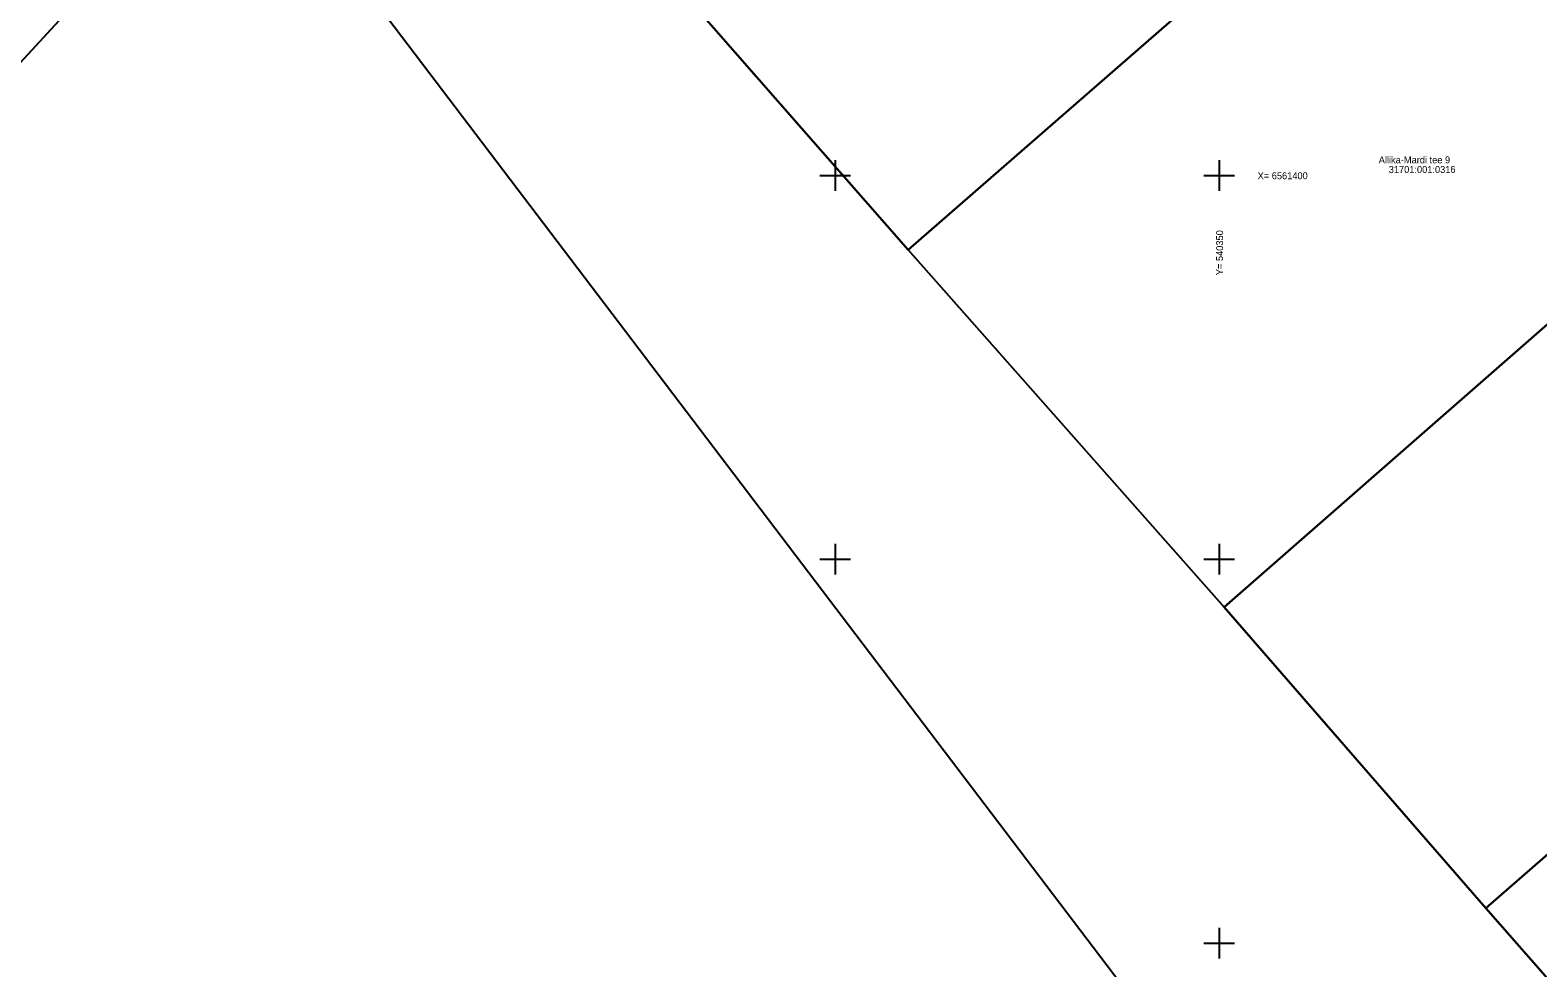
# Model space of a CAD drawing. Extents: x 538599 to 541973, y 6559689 to 6564516.
# Drawn here: x 540195.2 to 540391.5, y 6561296.8 to 6561418.9 of the extents above; entities that cross this region are included whole.
import ezdxf

# ---------------------------------------------------------------- set-up
doc = ezdxf.new("R2010")
doc.units = 0
for name, color, linetype in [('PIIR', 7, 'Continuous'), ('VORK', 7, 'Continuous'), ('VORMISTUS', 7, 'Continuous')]:
    doc.layers.add(name, color=color, linetype=linetype)

msp = doc.modelspace()

# ---------------------------------------------------------------- linework, layer by layer
at = {"layer": 'PIIR'}
msp.add_lwpolyline([(540274.62, 6561658.98), (540308.95, 6561626.96), (540342.1, 6561660.8), (540380.29, 6561616.49), (540315.96, 6561547.42), (540242.15, 6561467.11), (540086.59, 6561298.21), (539860.44, 6561301.54), (539867.53, 6561320.47), (539886.51, 6561388.42), (539892.89, 6561422.22), (539899.82, 6561444.13), (539930.12, 6561502.67), (539948.68, 6561538.36), (539974.66, 6561584.65), (539991.12, 6561609.35), (540012.97, 6561633.62), (540053.54, 6561681.61)], dxfattribs=at)
for points in [[(540275.86, 6561428.73), (540346.17, 6561499.11), (540384.55, 6561455.73), (540309.49, 6561390.29)], [(540086.59, 6561298.21), (540242.15, 6561467.11), (540275.86, 6561428.73), (540309.49, 6561390.29), (540350.66, 6561343.77), (540384.73, 6561304.57), (540422.29, 6561261.69), (540458.8, 6561220.37), (540491.21, 6561183.5), (540499, 6561174.36), (540490.55, 6561169.03), (539847.51, 6560731.53), (539695.32, 6560914.32), (539729.44, 6560945.74), (539769.27, 6560982.22), (539923.85, 6561123.78), (539979.73, 6561200.97), (540031.35, 6561186.14), (540104.75, 6561275.5)], [(540309.49, 6561390.29), (540384.55, 6561455.73), (540424.68, 6561408.57), (540350.66, 6561343.77)], [(540350.66, 6561343.77), (540424.68, 6561408.57), (540458.27, 6561368.69), (540384.73, 6561304.57)], [(540384.73, 6561304.57), (540458.27, 6561368.69), (540494.34, 6561324.62), (540422.29, 6561261.69)]]:
    msp.add_lwpolyline(points, close=True, dxfattribs=at)
at = {"layer": 'VORK'}
for p, q in [((540300, 6561402), (540300, 6561398)), ((540350, 6561402), (540350, 6561398)), ((540298, 6561400), (540302, 6561400)), ((540348, 6561400), (540352, 6561400)), ((540300, 6561352), (540300, 6561348)), ((540350, 6561352), (540350, 6561348)), ((540298, 6561350), (540302, 6561350)), ((540348, 6561350), (540352, 6561350)), ((540350, 6561302), (540350, 6561298)), ((540348, 6561300), (540352, 6561300))]:
    msp.add_line(p, q, dxfattribs=at)
at = {"layer": 'VORMISTUS'}
msp.add_lwpolyline([(540437.61, 6561637.11), (540710.79, 6561277.18), (540482.18, 6561103.67), (540209, 6561463.6)], close=True, dxfattribs=at)

# ---------------------------------------------------------------- texts
at = {"layer": 'PIIR'}
for s, p in [('Allika-Mardi tee 9', (540370.77, 6561401.57)), ('31701:001:0316', (540372.07, 6561400.32))]:
    msp.add_text(s, height=0.9, rotation=0, dxfattribs=at).set_placement(p)
at = {"layer": 'VORK'}
msp.add_text('X= 6561400', height=0.9, dxfattribs=at).set_placement((540355, 6561399.5))
msp.add_text('Y= 540350', height=0.9, rotation=90, dxfattribs=at).set_placement((540350.5, 6561387))

doc.saveas('drawing.dxf')
